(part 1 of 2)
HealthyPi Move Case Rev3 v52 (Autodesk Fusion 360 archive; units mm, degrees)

design "HealthyPi Move Case Rev3" references "Display assembly", "pc_healthypi_move_sensor_dual", "pc_healthypi_move_bottom_pcb_v2", "pc_healthypi_move_nRF5340_v3"
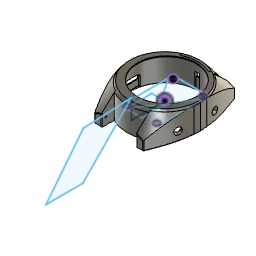
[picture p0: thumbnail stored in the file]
sketch "Main Body" plane through (0, 0, 0) normal (0, 0, 1) x axis (1, 0, 0)
  line L1 (30, -0.1178) -> (0, -0.1178)
  line L2 (0, 22) -> (0, 0)
  line L3 (0, 27.5644) -> (0, 22)
  line L4 (0, 22) -> (0, 27.5644)
  line L5 (10.6623, 27.5644) -> (0, 27.5644)
  line L6 (0, 27.5644) -> (10.6623, 27.5644)
  line L7 (10.6623, 35) -> (10.6623, 27.5644)
  line L8 (10.6623, 27.5644) -> (10.6623, 35)
  line L9 (10.6623, 19.0081) -> (10.6623, 27.5644)
  line L10 (10.6623, 27.5644) -> (10.6623, 19.0081)
  line L11 (15.1791, 27.5644) -> (10.6623, 27.5644)
  curve K1 (21.9997, -0.1178) -> (15.1791, 27.5644)
  curve K2 (22.274, -3.701) -> (21.7253, 3.4655)
  curve K3 (17.031, 22.6753) -> (13.3272, 32.4535)
  curve K4 (-21.9997, -0.1178) -> (-15.1791, 27.5644)
  curve K5 (-17.031, 22.6753) -> (-13.3272, 32.4535)
  curve K6 (-22.274, -3.701) -> (-21.7253, 3.4655)
  line L12 (-10.6623, 19.0081) -> (-10.6623, 27.5644)
  line L13 (-15.1791, 27.5644) -> (-10.6623, 27.5644)
  line L14 (-15.1791, -27.7999) -> (-10.6623, -27.7999)
  line L15 (-10.6623, -19.2436) -> (-10.6623, -27.7999)
  line L16 (10.6623, -19.2436) -> (10.6623, -27.7999)
  line L17 (10.6623, -27.7999) -> (10.6623, -19.2436)
  line L18 (15.1791, -27.7999) -> (10.6623, -27.7999)
  point P1 (0, 0)
  point P4 (0, 0)
  point P11 (21.9997, -0.1178)
  point P10 (15.1791, 27.5644)
  point P7 (10.6623, 27.5644)
  point P22 (-10.6623, 27.5644)
  point P9 (10.6623, 19.0081)
  point P23 (-10.6623, 19.0081)
  point P16 (-15.1791, 27.5644)
  point P17 (-21.9997, -0.1178)
  point P12 (21.7253, 3.4655)
  point P20 (-21.7253, 3.4655)
  point P13 (22.274, -3.701)
  point P21 (-22.274, -3.701)
  point P14 (13.3272, 32.4535)
  point P18 (-13.3272, 32.4535)
  point P15 (17.031, 22.6753)
  point P19 (-17.031, 22.6753)
  point P27 (10.6623, -27.7999)
  point P28 (10.6623, -19.2436)
  point P29 (15.1791, -27.7999)
  point P24 (-15.1791, -27.7999)
  point P25 (-10.6623, -27.7999)
  point P26 (-10.6623, -19.2436)
  horizontal L1
  coincident P1 P4
  perpendicular L1 L2
  parallel L2 L3
  perpendicular L4 L5
  perpendicular L6 L7
  perpendicular L6 L10
  perpendicular L8 L11
  coincident L1 P11
  midpoint P11 K2
  midpoint P10 K3
  symmetric L3 P7 P22
  symmetric L3 P9 P23
  symmetric L3 P10 P16
  symmetric L3 P11 P17
  symmetric L3 P12 P20
  symmetric L3 P13 P21
  symmetric L3 P14 P18
  symmetric L3 P15 P19
  symmetric L1 P7 P27
  symmetric L1 P9 P28
  symmetric L1 P10 P29
  symmetric L1 P16 P24
  symmetric L1 P22 P25
  symmetric L1 P23 P26
component_insert "Component Insert5"
position "Position2"
position "Position3"
position "Position4"
sketch "Bezel" plane through (0, 0, 5.0236) normal (0, 0, 1) x axis (-1, 0, 0)
  circle C1 centre (0.2, -0.9104) radius 18
  circle C2 centre (0, 0) radius 21.5
  circle C3 centre (0.2, -0.803) radius 19.25
  point P1 (0, 0)
  point P3 (0, 0)
  coincident P1 P3
  dimension "d25" diameter C1 = 36
  dimension "d26" diameter C2 = 43
  dimension "d47" diameter C3 = 38.5
extrude "Extrude12" new body sketch "Main Body" profile of L9 L10 L11 K1 K4 L12 L13 L14 L15 L16 L17 L18 along normal blind 10
combine "Combine4"
extrude "Extrude16" new body sketch "Bezel" blind 1 from offset 5 bodies "Bezel"
extrude "Extrude17" cut sketch "Bezel" profile of C1 C3 blind 0.5 from offset 5
position "Position8"
sketch "Sketch7" plane through (0, 0, 5.0236) normal (0, 0, 1) x axis (-1, 0, 0)
  line L1 (-6.8038, 19.9314) -> (-8.7325, 15.7942)
  line L2 (7.3694, 19.9373) -> (-6.8038, 19.9314)
  line L3 (9.3015, 15.8017) -> (7.3694, 19.9373)
  line L4 (-13.4784, -7.3014) -> (-13.4783, -7.4838)
  line L5 (-8.7059, 8.7198) -> (-8.5086, 9.6089)
  line L6 (-8.4449, 8.7199) -> (-8.7059, 8.7198)
  line L7 (-8.351, 9.2142) -> (-8.4449, 8.7199)
  line L8 (-8.2135, 8.72) -> (-8.351, 9.2142)
  line L9 (-7.9548, 8.7201) -> (-8.2135, 8.72)
  line L10 (-7.8171, 9.215) -> (-7.9548, 8.7201)
  line L11 (-7.7222, 8.7202) -> (-7.8171, 9.215)
  line L12 (-7.4624, 8.7204) -> (-7.7222, 8.7202)
  line L13 (-8.2399, 9.609) -> (-8.084, 9.0492)
  line L14 (-8.5086, 9.6089) -> (-8.2399, 9.609)
  line L15 (-6.3267, 8.9653) -> (-6.5836, 8.9652)
  line L16 (-5.8231, 8.9655) -> (-6.0722, 8.9654)
  line L17 (-2.3777, 9.6115) -> (-2.1297, 9.6116)
  line L18 (-7.6716, 12.2436) -> (-7.5008, 12.2437)
  line L19 (-7.6716, 12.072) -> (-7.6716, 12.2436)
  line L20 (-7.5008, 12.0721) -> (-7.6716, 12.072)
  line L21 (-7.5008, 12.2437) -> (-7.5008, 12.0721)
  line L22 (-6.2326, 12.0988) -> (-6.8381, 12.0985)
  line L23 (-6.2326, 12.2442) -> (-6.2326, 12.0988)
  line L24 (-7.0482, 12.2439) -> (-6.2326, 12.2442)
  curve K1 (-6.8648, 11.3801) -> (-7.0482, 12.2439)
  curve K2 (-7.05, 12.163) -> (-7.0482, 12.2439)
  curve K3 (-7.0132, 12.0893) -> (-7.05, 12.163)
  curve K4 (-6.9713, 12.0285) -> (-7.0132, 12.0893)
  curve K5 (-6.9295, 11.9677) -> (-6.9713, 12.0285)
  curve K6 (-6.8825, 11.9197) -> (-6.9295, 11.9677)
  curve K7 (-6.817, 11.8627) -> (-6.8825, 11.9197)
  curve K8 (-6.7515, 11.8057) -> (-6.817, 11.8627)
  curve K9 (-6.6674, 11.7397) -> (-6.7515, 11.8057)
  curve K10 (-6.6014, 11.6792) -> (-6.6674, 11.7397)
  curve K11 (-6.5683, 11.6489) -> (-6.6014, 11.6792)
  curve K12 (-6.5398, 11.62) -> (-6.5683, 11.6489)
  curve K13 (-6.5182, 11.5983) -> (-6.5398, 11.62)
  curve K14 (-6.4966, 11.5767) -> (-6.5182, 11.5983)
  curve K15 (-6.4819, 11.5622) -> (-6.4966, 11.5767)
  curve K16 (-6.4605, 11.5312) -> (-6.4819, 11.5622)
  curve K17 (-6.4391, 11.5001) -> (-6.4605, 11.5312)
  curve K18 (-6.4111, 11.4524) -> (-6.4391, 11.5001)
  curve K19 (-6.3974, 11.4106) -> (-6.4111, 11.4524)
  curve K20 (-6.3838, 11.3688) -> (-6.3974, 11.4106)
  curve K21 (-6.3846, 11.3329) -> (-6.3838, 11.3688)
  curve K22 (-6.3936, 11.299) -> (-6.3846, 11.3329)
  curve K23 (-6.4118, 11.231) -> (-6.3936, 11.299)
  curve K24 (-6.4632, 11.1706) -> (-6.4118, 11.231)
  curve K25 (-6.5363, 11.1463) -> (-6.4632, 11.1706)
  curve K26 (-6.6094, 11.122) -> (-6.5363, 11.1463)
  curve K27 (-6.7042, 11.1337) -> (-6.6094, 11.122)
  curve K28 (-6.7678, 11.175) -> (-6.7042, 11.1337)
  curve K29 (-6.8314, 11.2162) -> (-6.7678, 11.175)
  curve K30 (-6.8638, 11.2871) -> (-6.8314, 11.2162)
  curve K31 (-6.8648, 11.3801) -> (-6.8638, 11.2871)
  line L25 (-7.0193, 11.3646) -> (-6.8648, 11.3801)
  curve K32 (-6.8381, 12.0985) -> (-7.0193, 11.3646)
  curve K33 (-7, 11.1568) -> (-7.0193, 11.3646)
  curve K34 (-6.8702, 11.0355) -> (-7, 11.1568)
  curve K35 (-6.6851, 11.0135) -> (-6.8702, 11.0355)
  curve K36 (-6.5925, 11.0026) -> (-6.6851, 11.0135)
  curve K37 (-6.4862, 11.0164) -> (-6.5925, 11.0026)
  curve K38 (-6.4075, 11.0575) -> (-6.4862, 11.0164)
  curve K39 (-6.3288, 11.0985) -> (-6.4075, 11.0575)
  curve K40 (-6.2777, 11.1668) -> (-6.3288, 11.0985)
  curve K41 (-5.7561, 11.2301) -> (-6.2505, 11.2427)
  curve K42 (-5.7561, 11.2301) -> (-6.2233, 11.3186)
  curve K43 (-6.2199, 11.4021) -> (-6.2233, 11.3186)
  curve K44 (-6.2636, 11.4952) -> (-6.2199, 11.4021)
  curve K45 (-6.2855, 11.5417) -> (-6.2636, 11.4952)
  curve K46 (-6.3191, 11.5906) -> (-6.2855, 11.5417)
  curve K47 (-6.3478, 11.6263) -> (-6.3191, 11.5906)
  curve K48 (-6.3764, 11.662) -> (-6.3478, 11.6263)
  curve K49 (-6.4, 11.6846) -> (-6.3764, 11.662)
  curve K50 (-6.4285, 11.7113) -> (-6.4, 11.6846)
  curve K51 (-6.4569, 11.7381) -> (-6.4285, 11.7113)
  curve K52 (-6.4903, 11.769) -> (-6.4569, 11.7381)
  curve K53 (-6.5334, 11.8067) -> (-6.4903, 11.769)
  curve K54 (-6.5766, 11.8444) -> (-6.5334, 11.8067)
  curve K55 (-6.6295, 11.8888) -> (-6.5766, 11.8444)
  curve K56 (-6.6689, 11.9222) -> (-6.6295, 11.8888)
  curve K57 (-6.7084, 11.9556) -> (-6.6689, 11.9222)
  curve K58 (-6.7344, 11.9779) -> (-6.7084, 11.9556)
  curve K59 (-6.7615, 12.0049) -> (-6.7344, 11.9779)
  curve K60 (-6.7886, 12.0319) -> (-6.7615, 12.0049)
  curve K61 (-6.817, 12.0636) -> (-6.7886, 12.0319)
  curve K62 (-6.8381, 12.0985) -> (-6.817, 12.0636)
  curve K63 (-5.5861, 11.5776) -> (-5.2404, 11.5778)
  curve K64 (-5.148, 11.609) -> (-5.2404, 11.5778)
  curve K65 (-5.082, 11.6618) -> (-5.148, 11.609)
  curve K66 (-5.045, 11.7364) -> (-5.082, 11.6618)
  curve K67 (-5.008, 11.8111) -> (-5.045, 11.7364)
  curve K68 (-5, 11.9074) -> (-5.008, 11.8111)
  curve K69 (-5.0223, 11.9921) -> (-5, 11.9074)
  curve K70 (-5.0447, 12.0767) -> (-5.0223, 11.9921)
  curve K71 (-5.0973, 12.1496) -> (-5.0447, 12.0767)
  curve K72 (-5.1709, 12.1974) -> (-5.0973, 12.1496)
  curve K73 (-5.2444, 12.2453) -> (-5.1709, 12.1974)
  curve K74 (-5.3389, 12.2681) -> (-5.2444, 12.2453)
  curve K75 (-5.4319, 12.2648) -> (-5.3389, 12.2681)
  curve K76 (-5.5249, 12.2615) -> (-5.4319, 12.2648)
  curve K77 (-5.6163, 12.2322) -> (-5.5249, 12.2615)
  curve K78 (-5.6839, 12.18) -> (-5.6163, 12.2322)
  curve K79 (-5.7514, 12.1277) -> (-5.6839, 12.18)
  curve K80 (-5.795, 12.0524) -> (-5.7514, 12.1277)
  curve K81 (-5.8124, 11.9697) -> (-5.795, 12.0524)
  curve K82 (-5.8297, 11.8869) -> (-5.8124, 11.9697)
  curve K83 (-5.8208, 11.7966) -> (-5.8297, 11.8869)
  curve K84 (-5.783, 11.7254) -> (-5.8208, 11.7966)
  curve K85 (-5.7451, 11.6541) -> (-5.783, 11.7254)
  curve K86 (-5.6784, 11.6019) -> (-5.7451, 11.6541)
  curve K87 (-5.5861, 11.5776) -> (-5.6784, 11.6019)
  curve K88 (-5.2404, 11.5778) -> (-5.5861, 11.5776)
  curve K89 (-5.664, 11.5489) -> (-5.5861, 11.5776)
  curve K90 (-5.7174, 11.5063) -> (-5.664, 11.5489)
  curve K91 (-5.7459, 11.4438) -> (-5.7174, 11.5063)
  curve K92 (-5.7744, 11.3813) -> (-5.7459, 11.4438)
  curve K93 (-5.778, 11.2988) -> (-5.7744, 11.3813)
  curve K94 (-5.7561, 11.2301) -> (-5.778, 11.2988)
  curve K95 (-5.7122, 11.0926) -> (-5.7561, 11.2301)
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  point P203 (4.5577, 11.8033)
  point P204 (4.5577, 11.8033)
  coincident P203 P204
extrude "Extrude18" new body sketch "Sketch7" along normal blind 10
move "Move11"
move_face "MoveFace3"
move_face "MoveFace4"
move_face "MoveFace5"
move_face "MoveFace6"
move_face "MoveFace7"
move_face "MoveFace8" TranslateX -65 TranslateY 0 TranslateZ 0
move "Move12" TranslateX -64 TranslateY 0 TranslateZ 0
move "Move13" TranslateX 0 TranslateY 0 TranslateZ -5
move "Move14" TranslateX 0 TranslateY 0 TranslateZ -1
position "Position9"
combine "Combine6"
sketch "Bottom PCB cover" plane through (0, 0, 0) normal (0, 0, 1) x axis (1, 0, 0)
  line L1 (0, 25) -> (0, 0)
  line L2 (25.4334, 0) -> (0, 0)
  circle C1 centre (-0.0004, -0.032) radius 21
  arc A1 centre (13.7643, 16.9724) radius 3.8181 clockwise from (10.1946, 18.3272) to (15.8328, 13.7632)
  circle C2 centre (14.2643, 17.721) radius 1
  arc A2 centre (-13.7643, 16.9724) radius 3.8181 clockwise from (-15.8328, 13.7632) to (-10.1946, 18.3272)
  circle C3 centre (-14.2643, 17.721) radius 1
  arc A3 centre (-13.7643, -16.9724) radius 3.8181 clockwise from (-10.1946, -18.3272) to (-15.8328, -13.7632)
  circle C4 centre (-14.2643, -17.721) radius 1
  arc A4 centre (13.7643, -16.9724) radius 3.8181 clockwise from (15.8328, -13.7632) to (10.1946, -18.3272)
  circle C5 centre (14.2643, -17.721) radius 1
  point P1 (0, 0)
  point P3 (0, 0)
  point P5 (0, 0)
  point P8 (15.8328, 13.7632)
  point P7 (10.1946, 18.3272)
  point P13 (-10.1946, 18.3272)
  point P12 (-15.8328, 13.7632)
  point P22 (10.1946, -18.3272)
  point P21 (15.8328, -13.7632)
  point P18 (-15.8328, -13.7632)
  point P17 (-10.1946, -18.3272)
  coincident P1 P3
  vertical L1
  coincident P1 P5
  perpendicular L1 L2
  coincident C1 P8
  coincident C1 P7
  symmetric L1 P7 P13
  symmetric L1 P8 P12
  symmetric L1 A1 A2
  symmetric L1 C2 C3
  symmetric L2 P7 P22
  symmetric L2 P8 P21
  symmetric L2 A1 A4
  symmetric L2 C2 C5
  symmetric L2 P12 P18
  symmetric L2 P13 P17
  symmetric L2 A2 A3
  symmetric L2 C3 C4
  dimension "d79" diameter C1 = 42
  dimension "d81" diameter C2 = 2
extrude "Extrude19" new body sketch "Bottom PCB cover" profile of C1 A1 C2 along normal blind 1
extrude "Extrude21" new body sketch "Bottom PCB cover" profile of C1 A1 C2 A2 C3 A3 C4 A4 C5 blind 1 from offset -5 bodies "Bottom cover"
move "Move15"
copy_paste_bodies "CopyPasteBodies2"
move "Move16" TranslateX 0 TranslateY 32 TranslateZ 0
move "Move17"
move "Move18"
combine "Combine7" bodies "Bottom cover"
move "Move19"
fillet "Fillet1" radius 1.2
fillet "Fillet2" radius 0.6
delete_face "DeleteFace1"
fillet "Fillet3" radius 0.5
move_face "MoveFace9"
move "Move20"
fillet "Fillet4" radius 0.5
fillet "Fillet5" radius 0.9
component_insert "Component Insert6"
move "Move21"
position "Position10"
sketch "Cutter" plane through (0, 0, 0) normal (1, 0, 0) x axis (0, 1, 0)
  line L1 (-20.5, 0) -> (0, 0)
  line L2 (-73.0459, -18.6004) -> (-50.3996, -18.602)
  line L3 (-73.0459, -18.6004) -> (-50.0889, 10.5658)
  line L4 (-50.0889, 10.5658) -> (-20.5, 12)
  line L5 (-20.5, 12) -> (-20.5, 0)
  line L6 (-50.3996, -18.602) -> (-20.5, 12)
  point P1 (0, 0)
  point P2 (0, 0)
  point P7 (-50.3996, -18.602)
  point P3 (-20.5, 0)
  coincident P1 P2
  horizontal L1
  perpendicular L1 L5
  coincident L2 P7
  dimension "d104" distance P2 P3 = 20.5
move "Move22"
move "Move23"
move "Move24" TranslateX -1 TranslateY 0 TranslateZ 0
revolve "Revolve1" sketch "Cutter" AlongAngle 360 AgainstAngle 0
fillet "Fillet6" radius 0.4
fillet "Fillet7" radius 0.5
offset_faces "OffsetFaces7" distance -4
offset_faces "OffsetFaces8" distance -4
offset_faces "OffsetFaces9" distance -4
offset_faces "OffsetFaces10" distance -4
extrude "Extrude22" cut blind -2
delete_face "DeleteFace2"
cylinder_primitive "CylinderPrimitive1" Height 22 Diameter 1.142
move_face "MoveFace10" TranslateX -2 TranslateY 0 TranslateZ 5
move_face "MoveFace11" TranslateX 0 TranslateY 19 TranslateZ 0
move_face "MoveFace12" TranslateX 0 TranslateY 50 TranslateZ 0
move_face "MoveFace13" TranslateX 0 TranslateY 0 TranslateZ 11
offset_faces "OffsetFaces11" distance 6
move "Move25" TranslateX 3 TranslateY 0 TranslateZ 0
move "Move26" TranslateX 0 TranslateY 0 TranslateZ -11
move "Move27" TranslateX 3 TranslateY 3 TranslateZ -2
move "Move28" TranslateX -3 TranslateY 0 TranslateZ 0
move_face "MoveFace14" TranslateX 0 TranslateY -3 TranslateZ 0
move_face "MoveFace15" TranslateX 0 TranslateY -1 TranslateZ 0
move_face "MoveFace16" TranslateX 45 TranslateY 0 TranslateZ 0
copy_paste_bodies "CopyPasteBodies3"
move "Move29"
move_face "MoveFace17" TranslateX 2 TranslateY 0 TranslateZ 0
move "Move30" TranslateX 1 TranslateY 0 TranslateZ 0
move "Move31" TranslateX -0.5 TranslateY 0 TranslateZ 0
copy_paste_bodies "CopyPasteBodies4"
move "Move32"
combine "Combine8"
combine "Combine9"
fillet "Fillet8" radius 0.4
move "Move33"
move "Move34"
move_face "MoveFace18"
move "Move35"
move "Move36"
position "Position11"
sketch "Sketch18" plane through (0, 0, 11.0236) normal (0, 0, 1) x axis (-1, 0, 0)
  circle C1 centre (0.2, -0.9104) radius 18
  arc A1 centre (0, 0) radius 20 clockwise from (8.1514, 18.2635) to (-7.4412, 18.5642)
  circle C2 centre (0, 0) radius 20.6
offset_faces "OffsetFaces12" distance -0.2
offset_faces "OffsetFaces13" distance -0.2
offset_faces "OffsetFaces14" distance -0.2
offset_faces "OffsetFaces15" distance -0.2
move "Move37"
delete_face "DeleteFace3"
delete_face "DeleteFace4"
delete_face "DeleteFace5"
delete_face "DeleteFace6"
component_insert "Component Insert10"
component_insert "Component Insert11"
offset_faces "OffsetFaces16" distance 4.7
delete_face "DeleteFace7"
offset_faces "OffsetFaces17" sketch "Switch Up" distance -0.25
move "Move38"
move "Move39"
move_face "MoveFace19"
move "Move40"
copy_paste_bodies "CopyPasteBodies5"
move "Move41"
move "Move42"
move "Move43"
position "Position12"
combine "Combine10"
sketch "USB Cutout" plane through (-19.6479, 0, 0) normal (-1, 0, 0) x axis (0, -1, 0)
  line L1 (3.2369, -0.6999) -> (0.8269, -0.6999)
  line L2 (4.5369, 1.1601) -> (4.5369, 0.6001)
  line L3 (-3.1031, 2.4601) -> (3.2369, 2.4601)
  line L4 (-4.4031, 0.6001) -> (-4.4031, 1.1601)
  line L5 (1.8168, -1.7283) -> (-0.1732, -1.7418)
  line L6 (3.2821, -1.6995) -> (1.8168, -1.7283)
  line L7 (5.5369, 1.1601) -> (5.5369, 0.6001)
  line L8 (-3.1031, 3.4601) -> (3.2369, 3.4601)
  line L9 (-5.4031, 0.6001) -> (-5.4031, 1.1601)
  line L10 (-0.1732, -1.7418) -> (-3.1358, -1.6997)
  line L11 (0.8269, -0.6999) -> (-3.1031, -0.6999)
  arc A1 centre (3.2369, 0.6001) radius 1.3 clockwise from (4.5369, 0.6001) to (3.2369, -0.6999)
  arc A2 centre (3.2369, 1.1601) radius 1.3 clockwise from (3.2369, 2.4601) to (4.5369, 1.1601)
  arc A3 centre (-3.1031, 1.1601) radius 1.3 clockwise from (-4.4031, 1.1601) to (-3.1031, 2.4601)
  arc A4 centre (-3.1031, 0.6001) radius 1.3 clockwise from (-3.1031, -0.6999) to (-4.4031, 0.6001)
  arc A5 centre (3.2369, 0.6001) radius 2.3 clockwise from (5.5369, 0.6001) to (3.2821, -1.6995)
  arc A6 centre (3.2369, 1.1601) radius 2.3 clockwise from (3.2369, 3.4601) to (5.5369, 1.1601)
  arc A7 centre (-3.1031, 1.1601) radius 2.3 clockwise from (-5.4031, 1.1601) to (-3.1031, 3.4601)
  arc A8 centre (-3.1031, 0.6001) radius 2.3 clockwise from (-3.1358, -1.6997) to (-5.4031, 0.6001)
  concentric A1 A5
  concentric A2 A6
  concentric A3 A7
  concentric A4 A8
  tangent A8 L10
  tangent L9 A8
  tangent A7 L9
  tangent L8 A7
  tangent L7 A6
  tangent A5 L7
  tangent A6 L8
  tangent L6 A5
  tangent A4 L11
extrude "Extrude23" new body sketch "USB Cutout" profile of L10 A8 L9 A7 L8 A6 L7 A5 L6 along normal blind 6 and along normal blind 5 bodies "USB Offset"
combine "Combine11"
offset_faces "OffsetFaces18" sketch "Switch Up" distance -10
sketch "Side Electrode" plane through (0, 0, 0) normal (0, 1, 0) x axis (1, 0, 0)
  line L1 (9.25, -10) -> (9.25, 0)
  line L2 (-9.25, -10) -> (9.25, -10)
  line L3 (-9.25, -10) -> (-9.25, 0)
  line L4 (-9.25, 0) -> (-9.25, -10)
  line L5 (9.25, -10) -> (9.25, 0)
  line L6 (-9.25, 0) -> (9.25, 0)
  line L7 (9.25, -11) -> (9.25, -10)
  line L8 (-9.25, -11) -> (9.25, -11)
  line L9 (10.6358, -11) -> (9.25, -11)
  line L10 (10.6358, 1.4792) -> (10.6358, -11)
  line L11 (-10.6951, 1.4792) -> (10.6358, 1.4792)
  line L12 (-10.6951, -11) -> (-10.6951, 1.4792)
  line L13 (-9.25, -11) -> (-10.6951, -11)
  line L14 (-1.6047, -5.118) -> (1.3953, -5.118)
  line L15 (-1.6047, -2.118) -> (-1.6047, -5.118)
  line L16 (1.3953, -2.118) -> (-1.6047, -2.118)
  line L17 (1.3953, -5.118) -> (1.3953, -2.118)
  point P2 (9.25, 0)
  point P3 (9.25, -10)
  point P4 (-9.25, -10)
  point P6 (9.25, -11)
  point P7 (-9.25, -11)
  point P12 (1.3953, -5.118)
  point P13 (-1.6047, -5.118)
  point P14 (-1.6047, -2.118)
  perpendicular L1 L2
  perpendicular L4 L6
  perpendicular L2 L7
  perpendicular L7 L8
  perpendicular L7 L9
  perpendicular L8 L10
  perpendicular L10 L11
  perpendicular L11 L12
  perpendicular L12 L13
  parallel L2 L14
  perpendicular L14 L15
  perpendicular L15 L16
  perpendicular L14 L17
  dimension "d191" distance P2 P3 = 10
  dimension "d192" distance P3 P4 = 18.5
  dimension "d357" distance P3 P6 = 1
  dimension "d358" distance P6 P7 = 18.5
  dimension "d397" distance P12 P13 = 3
  dimension "d398" distance P13 P14 = 3
extrude "Extrude26" new body sketch "Side Electrode" profile of L1 L2 L3 along normal blind 1 bodies "Side Electrode"
move "Move44"
offset_faces "OffsetFaces19" distance 1
move_face "MoveFace20"
extrude "Extrude27" new body sketch "Side Electrode" profile of L1 L2 L3 blind 3 from offset 20 bodies "Side Electrode Holder"
move_face "MoveFace21"
move "Move45"
move "Move46"
extrude "Extrude28" cut of existing geometry blind 1
sketch "Bottom Cutout" plane through (0, 0, 0) normal (0, 0, 1) x axis (1, 0, 0)
  line L1 (-15.7, 13.9) -> (-15.9707, 14.0974)
  line L2 (-15.9707, 14.0974) -> (-16.2232, 14.3176)
  line L3 (-10.9272, 19.8796) -> (-10.6949, 19.6383)
  line L4 (-10.6949, 19.6383) -> (-10.4845, 19.3776)
  line L5 (-10, 18.5) -> (-8.2535, 19.3144)
  line L6 (10.4, 18.5) -> (10.5357, 18.8063)
  line L7 (10.8845, 19.3776) -> (11.0949, 19.6383)
  line L8 (11.0949, 19.6383) -> (11.3272, 19.8796)
  line L9 (11.8504, 20.2972) -> (12.1372, 20.4702)
  line L10 (16.1, 13.9) -> (17.236, 12.4195)
  line L11 (16.1, -13.6) -> (16.3707, -13.7974)
  line L12 (17.2527, -14.7977) -> (17.4146, -15.0909)
  line L13 (10.5357, -18.5063) -> (10.4, -18.2)
  line L14 (10.4, -18.2) -> (10, -18.4)
  line L15 (-10, -18.2) -> (-10.1357, -18.5063)
  line L16 (-11.1797, -19.7998) -> (-11.4504, -19.9972)
  line L17 (-15.7, -13.6) -> (-16.836, -12.1195)
  line L18 (-10.3946, 19.9031) -> (-10.1679, 19.6222)
  line L19 (-10.6449, 20.1631) -> (-10.3946, 19.9031)
  line L20 (-16.2743, 13.8315) -> (-16.4925, 14.0218)
  line L21 (-16.2649, -13.5209) -> (-17.1587, -12.3561)
  line L22 (-10.9371, -20.118) -> (-11.2216, -20.3254)
  line L23 (10.2075, -18.7435) -> (10.18, -18.7572)
  line L24 (17.5988, -14.5969) -> (17.7689, -14.9051)
  line L25 (16.6649, 13.8209) -> (17.5586, 12.6561)
  line L26 (11.6365, 20.6353) -> (11.9379, 20.8171)
  line L27 (10.7946, 19.9031) -> (11.0449, 20.1631)
  line L28 (10.5679, 19.6222) -> (10.7946, 19.9031)
  line L29 (-9.8024, 19.0335) -> (-8.4146, 19.6806)
  circle C1 centre (14.4, -17.6) radius 1.25
  circle C2 centre (-14, 17.9) radius 1.25
  circle C3 centre (-14.1, -17.6) radius 1.25
  circle C4 centre (14.45, 17.95) radius 1.25
  arc A1 centre (0.6866, 0.15) radius 21.3912 clockwise from (-16.836, -12.1195) to (-15.7, 13.9)
  arc A2 centre (-13.5752, 17.0986) radius 3.84 clockwise from (-16.2232, 14.3176) to (-10.9272, 19.8796)
  arc A3 centre (-13.5753, 17.0986) radius 3.8401 clockwise from (-10.4845, 19.3776) to (-10, 18.5)
  arc A4 centre (0.2, -1.094) radius 22.0899 clockwise from (-8.2535, 19.3144) to (10.4, 18.5)
  arc A5 centre (13.9751, 17.0985) radius 3.84 clockwise from (10.5357, 18.8063) to (10.8845, 19.3776)
  arc A6 centre (13.9754, 17.0983) radius 3.8404 clockwise from (11.3272, 19.8796) to (11.8504, 20.2972)
  arc A7 centre (13.9752, 17.0986) radius 3.84 clockwise from (12.1372, 20.4702) to (16.1, 13.9)
  arc A8 centre (-0.2867, 0.15) radius 21.3912 clockwise from (17.236, 12.4195) to (16.1, -13.6)
  arc A9 centre (13.9752, -16.7986) radius 3.84 clockwise from (16.3707, -13.7974) to (17.2527, -14.7977)
  arc A10 centre (13.9751, -16.7986) radius 3.84 clockwise from (17.4146, -15.0909) to (10.5357, -18.5063)
  arc A11 centre (0.1921, 0.9099) radius 21.6579 clockwise from (10, -18.4) to (-10, -18.2)
  arc A12 centre (-13.5752, -16.7986) radius 3.84 clockwise from (-10.1357, -18.5063) to (-11.1797, -19.7998)
  arc A13 centre (-13.5752, -16.7986) radius 3.84 clockwise from (-11.4504, -19.9972) to (-15.7, -13.6)
  arc A14 centre (-13.5753, 17.0986) radius 4.2401 clockwise from (-10.1679, 19.6222) to (-9.8024, 19.0335)
  arc A15 centre (-13.5752, 17.0986) radius 4.24 clockwise from (-16.4925, 14.0218) to (-10.6449, 20.1631)
  arc A16 centre (0.6866, 0.15) radius 21.7912 clockwise from (-17.1587, -12.3561) to (-16.2743, 13.8315)
  arc A17 centre (-13.5752, -16.7986) radius 4.24 clockwise from (-11.2216, -20.3254) to (-16.2649, -13.5209)
  arc A18 centre (-13.5752, -16.7986) radius 4.24 clockwise from (-9.8107, -18.7496) to (-10.9371, -20.118)
  arc A19 centre (0.1921, 0.9099) radius 22.0579 clockwise from (10.18, -18.7572) to (-9.8107, -18.7496)
  arc A20 centre (13.9751, -16.7986) radius 4.24 clockwise from (17.7689, -14.9051) to (10.2075, -18.7435)
  arc A21 centre (13.9752, -16.7986) radius 4.24 clockwise from (16.6757, -13.5298) to (17.5988, -14.5969)
  arc A22 centre (-0.2867, 0.15) radius 21.7912 clockwise from (17.5586, 12.6561) to (16.6757, -13.5298)
  arc A23 centre (13.9752, 17.0986) radius 4.24 clockwise from (11.9379, 20.8171) to (16.6649, 13.8209)
  arc A24 centre (13.9754, 17.0983) radius 4.2404 clockwise from (11.0449, 20.1631) to (11.6365, 20.6353)
  arc A25 centre (13.9751, 17.0985) radius 4.24 clockwise from (10.2088, 19.046) to (10.5679, 19.6222)
  arc A26 centre (0.2, -1.094) radius 22.4899 clockwise from (-8.4146, 19.6806) to (10.2088, 19.046)
  dimension "d206" = 0.4
extrude "Extrude29" new body sketch "Bottom Cutout" blind 1 from offset -4 bodies "Bottom Cutout"
move "Move47"
move "Move48"
combine "Combine15" sketch "Switch Up"
extrude "Extrude30" cut sketch "USB Cutout" profile of L1 A1 L2 A2 L3 A3 L4 A4 L11 along normal blind 1
extrude "Extrude31" new body sketch "USB Cutout" profile of L1 A1 L2 A2 L3 A3 L4 A4 L11 along normal blind 5 and against normal blind 5 bodies "USB Cutout"
combine "Combine16"
sketch "Inside Fixture" plane through (0, 0, 0) normal (0, 0, 1) x axis (1, 0, 0)
  line L1 (-11.1264, -14.2668) -> (-11.1259, 14.2778)
  line L2 (9.3235, 16.1831) -> (-9.1186, 16.1823)
  line L3 (11.2736, -14.2669) -> (11.2733, 14.2003)
  line L4 (7.6879, -15.3284) -> (-10.8726, 13.2711)
  line L5 (10.9592, 13.1714) -> (-7.575, -15.3795)
  line L6 (2.0838, -16.0146) -> (-7.9872, -16.0146)
  line L7 (2.0838, 0) -> (2.0838, -16.0146)
  line L8 (-7.9872, 0) -> (2.0838, 0)
  line L9 (-7.9872, -16.0146) -> (-7.9872, 0)
  circle C1 centre (-9.1764, 14.2331) radius 1.25
  circle C2 centre (9.3236, 14.2331) radius 1.25
  circle C3 centre (9.3236, -14.2669) radius 1.25
  circle C4 centre (-9.1764, -14.2669) radius 1.25
  circle C5 centre (-9.1764, 14.2331) radius 1.95
  circle C6 centre (-9.1764, -14.2669) radius 1.95
  circle C7 centre (9.3236, 14.2331) radius 1.95
  circle C8 centre (9.3236, -14.2669) radius 1.95
  point P10 (-11.1259, 14.2778)
  point P11 (-11.1264, -14.2668)
  point P12 (-9.1186, 16.1823)
  point P13 (9.3235, 16.1831)
  point P14 (11.2733, 14.2003)
  point P15 (11.2736, -14.2669)
  point P16 (-10.8726, 13.2711)
  point P17 (7.6879, -15.3284)
  point P18 (-7.575, -15.3795)
  point P19 (10.9592, 13.1714)
  coincident C5 P10
  coincident C6 P11
  tangent C6 L1
  coincident C5 P12
  coincident C7 P13
  tangent C7 L2
  coincident C7 P14
  coincident C8 P15
  tangent C8 L3
  coincident C5 P16
  coincident C8 P17
  tangent C8 L4
  coincident C6 P18
  coincident C7 P19
  tangent C7 L5
  horizontal L6
  vertical L7
  horizontal L8
  vertical L9
  dimension "d246" = 0.7
  dimension "d247" = 0.7
  dimension "d248" = 0.7
  dimension "d249" = 0.7
extrude "Extrude32" new body sketch "Inside Fixture" + "Switch Up" blind 3 from offset 7 bodies "Internal Display holder"
move "Move49"
move "Move50"
extrude "Extrude33" add sketch "Inside Fixture" + "Switch Up" blind 1 from offset 6
move "Move51"
combine "Combine17"
combine "Combine18"
offset_faces "OffsetFaces22" distance -1
fillet "Fillet10" sketch "Switch Up" radius 10
fillet "Fillet11" radius 18
delete_face "DeleteFace8" sketch "Switch Up"
copy_paste_bodies "CopyPasteBodies6"
move "Move52" sketch "Switch Up"
copy_paste_bodies "CopyPasteBodies7"
move "Move53"
copy_paste_bodies "CopyPasteBodies8"
move "Move54" sketch "Switch Up"
offset_faces "OffsetFaces27" distance 5
offset_faces "OffsetFaces28" distance 6
offset_faces "OffsetFaces29" distance -4
combine "Combine20" sketch "Switch Up"
position "Position13"
move_face "MoveFace22"
offset_faces "OffsetFaces30" distance -5
offset_faces "OffsetFaces31" distance 0.7
position "Position14"
extrude "Extrude35" new body sketch "Inside Fixture" profile of C1 C2 C3 C4 along normal blind 1 bodies "Display bench"
extrude "Extrude36" add sketch "Inside Fixture" + "Switch Up" profile of S1:C1 S1:C2 S1:C3 S1:C4 blind -10.5
extrude "Extrude37" new body sketch "Inside Fixture" + "Switch Up" profile of S1:C1 S1:C2 S1:C3 S1:C4 S1:C5 S1:C6 S1:C7 S1:C8 S1:L1 S1:L4 S1:L5 blind -6.9
extrude "Extrude38" add sketch "Inside Fixture" profile of C1 C2 C3 C4 C5 C6 C7 C8 L1 L2 L3 L4 L5 along normal blind 1
sketch "Switch Up" plane through (17.9408, 8.7503, 0) normal (0.8988, 0.4384, 0) x axis (-0.4384, 0.8988, 0)
  circle C1 centre (-0.1243, 0.1978) radius 2
  circle C2 centre (-0.1243, 0.1978) radius 2.1
  circle C3 centre (-0.1243, 0.1978) radius 2.375
  circle C4 centre (-0.1243, 0.1978) radius 2.625
  concentric C1 C3
  concentric C3 C4
  dimension "d289" diameter C1 = 4
  dimension "d294" = 0.1
  dimension "d329" diameter C3 = 4.75
  dimension "d356" diameter C4 = 5.25
sketch "Switch Down" plane through (16.816, -10.5078, 0) normal (0.848, -0.5299, 0) x axis (0.5299, 0.848, 0)
  circle C1 centre (0.4524, 0.2039) radius 2
  circle C2 centre (0.4524, 0.2039) radius 2.1
  circle C3 centre (0.4524, 0.2039) radius 2.375
  circle C4 centre (0.4524, 0.2039) radius 2.625
  concentric C1 C3
  concentric C1 C4
  dimension "d299" diameter C1 = 4
  dimension "d304" = 0.1
  dimension "d330" diameter C3 = 4.75
  dimension "d355" diameter C4 = 5.25
move "Move57"
move "Move58"
extrude "Extrude47" cut sketch "Switch Up" profile of C1 C2 along normal blind 6 and against normal blind 0.5
extrude "Extrude49" cut sketch "Switch Down" profile of C1 C2 along normal blind 7 and against normal blind 0.5
delete_face "DeleteFace9" sketch "Switch Up"
extrude "Extrude50" new body sketch "Switch Up" along normal blind 0.8 and against normal blind 0.5
extrude "Extrude51" cut of existing geometry blind 5
extrude "Extrude52" new body sketch "Switch Down" along normal blind 0.8 and against normal blind 0.5
extrude "Extrude53" cut of existing geometry blind 9
position "Position5"
position "Position6"
position "Position7"
box_primitive "BoxPrimitive1" DistanceX 5 DistanceY 20 DistanceZ 20 OffsetDistanceX 0 OffsetDistanceY 0
move "Move5"
move "Move6"
move_face "MoveFace1"
move_face "MoveFace2"
move "Move7"
move "Move8"
move "Move9"
extrude "Extrude54" new body sketch "Side Electrode" profile of L1 L2 L3 L4 L5 blind 0.5 from offset 20
move "Move59"
move "Move60"
move "Move61"
fillet "Fillet12" radius 0.9
fillet "Fillet13" radius 0.9
sketch "Sketch33" plane through (0, 0, 0) normal (0, 0, 1) x axis (1, 0, 0)
  circle C1 centre (-0.2537, 0.8174) radius 19.25
move "Move62"
move "Move63"
offset_faces "OffsetFaces35" distance -4
extrude "Extrude56" cut sketch "Switch Down" profile of C1 C2 C3 along normal blind 1.5 and against normal blind 0.5
extrude "Extrude57" new body sketch "Switch Down" profile of C1 C2 C3 blind 0.8 from offset 0.7 bodies "SW Act Down"
extrude "Extrude58" add sketch "Switch Down" profile of C1 blind 5 from offset 1.5
extrude "Extrude59" cut sketch "Switch Up" profile of C1 C2 C3 along normal blind 1.5 and against normal blind 0.5
extrude "Extrude60" new body sketch "Switch Up" profile of C1 C2 C3 blind 0.8 from offset 0.7 bodies "SW Act Up"
extrude "Extrude61" add sketch "Switch Up" profile of C1 blind 5 from offset 1.5
move "Move64" sketch "Switch Up"
move "Move65"
extrude "Extrude62" new body sketch "Side Electrode" profile of L1 L2 L3 L4 L5 L6 blind 1 from offset 21 bodies "Electrode"
extrude "Extrude63" new body sketch "Side Electrode" profile of L1 L2 L3 L4 L5 L6 L8 L9 L10 L11 L12 L13 blind 3 from offset 20
offset_faces "OffsetFaces36" distance 1
move "Move66"
move "Move67"
combine "Combine25"
offset_faces "OffsetFaces37" distance 3
copy_paste_bodies "CopyPasteBodies11"
move "Move68"
move "Move69"
offset_faces "OffsetFaces38" distance 1
offset_faces "OffsetFaces39" distance 7
offset_faces "OffsetFaces40" distance 0.9
move "Move70"
extrude "Extrude64" add of existing geometry blind 11.03
delete_face "DeleteFace10"
delete_face "DeleteFace11"
move "Move71" sketch "Switch Up"
move "Move72"
delete_face "DeleteFace12"
delete_face "DeleteFace13"
move "Move73"
move "Move74"
combine "Combine31"
move "Move75"
combine "Combine32"
copy_paste_bodies "CopyPasteBodies12"
move "Move76"
offset_faces "OffsetFaces41" distance 1.41
move "Move77"
offset_faces "OffsetFaces42" distance 1.4
offset_faces "OffsetFaces43" distance 3
offset_faces "OffsetFaces44" distance 4
combine "Combine33" sketch "Switch Up"
fillet "Fillet15" sketch "Switch Up" radius 2
offset_faces "OffsetFaces45" sketch "Switch Up" distance -0.6
fillet "Fillet16" radius 1.55
fillet "Fillet18" sketch "Switch Up" radius 1
fillet "Fillet23" sketch "Switch Up" radius 2.25
extrude "Extrude65" new body sketch "Side Electrode" profile of L14 L15 L16 L17 blind 5 from offset 19
combine "Combine34"
extrude "Extrude66" new body sketch "Side Electrode" profile of L14 L15 L16 L17 blind 1 from offset 20
offset_faces "OffsetFaces46" distance 10
move "Move78"
combine "Combine35"
delete_face "DeleteFace15"
delete_face "DeleteFace16"
combine "Combine36"
sketch "Sketch34" plane through (0, 0, 0) normal (0, 0, 1) x axis (1, 0, 0)
  line L1 (10.6623, -19.4449) -> (10.6623, -27.1999)
  line L2 (-10.6623, -27.1999) -> (-10.6623, -19.8797)
  line L3 (-10.6623, -19.2436) -> (-10.6623, -19.8797)
  line L4 (10.6623, -19.2436) -> (10.6623, -19.4449)
  line L5 (10.6623, -19.2436) -> (10.5539, -19.3032)
  line L6 (10.6623, -18.0688) -> (10.6623, -19.2436)
  line L7 (-10.6623, -17.2035) -> (-10.6623, -19.1577)
  line L8 (-10.6623, -19.2436) -> (-10.6623, -19.1577)
  arc A1 centre (0, 0) radius 22 clockwise from (10.5539, -19.3032) to (-10.2707, -19.4554)
  arc A2 centre (0, 0) radius 22 clockwise from (-10.2707, -19.4554) to (-10.6623, -19.2436)
  arc A3 centre (0, 0) radius 23 clockwise from (11.0336, -20.1807) to (-10.7376, -20.3397)
  arc A4 centre (0, 0) radius 21.4147 clockwise from (10.6623, -18.5716) to (-10.6623, -18.5716)
  point P11 (-10.6623, -19.8797)
  point P13 (-10.6623, -19.8797)
  point P5 (-10.6623, -19.2436)
  point P14 (-10.6623, -19.2436)
  point P10 (10.6623, -19.4449)
  point P15 (10.6623, -19.4449)
  point P8 (10.6623, -19.2436)
  point P16 (10.6623, -19.2436)
  point P3 (10.5539, -19.3032)
  point P17 (10.5539, -19.3032)
  point P21 (10.6623, -19.2436)
  coincident P11 P13
  coincident P5 P14
  coincident P10 P15
  coincident P8 P16
  coincident P3 P17
  coincident P8 P21
  parallel L4 L6
  parallel L3 L7
  concentric A1 A4
  parallel L3 L8
  dimension "d406" = 1
extrude "Extrude67" new body sketch "Sketch34" profile of A1 A2 L1 L2 L3 L4 L5 A3 along normal blind 11 and against normal blind 5.3
delete_face "DeleteFace17" sketch "Switch Up"
delete_face "DeleteFace20"
delete_face "DeleteFace21" sketch "Switch Up"
delete_face "DeleteFace22"
delete_face "DeleteFace23"
delete_face "DeleteFace24" sketch "Switch Up"
delete_face "DeleteFace25"
delete_face "DeleteFace26"
delete_face "DeleteFace27"
delete_face "DeleteFace28" sketch "Switch Up"
delete_face "DeleteFace29"
move "Move80"
extrude "Extrude71" add of existing geometry blind -1
extrude "Extrude72" cut of existing geometry blind -0.9
extrude "Extrude73" cut of existing geometry blind -0.75
delete_face "DeleteFace52"
delete_face "DeleteFace53" sketch "Switch Up"
delete_face "DeleteFace54"
delete_face "DeleteFace55"
delete_face "DeleteFace56"
delete_face "DeleteFace57"
delete_face "DeleteFace58"
delete_face "DeleteFace59"
delete_face "DeleteFace60"
delete_face "DeleteFace61"
delete_face "DeleteFace62" sketch "Switch Up"
delete_face "DeleteFace63"
delete_face "DeleteFace64"
delete_face "DeleteFace65"
delete_face "DeleteFace66"
delete_face "DeleteFace67" sketch "Switch Up"
delete_face "DeleteFace68"
fillet "Fillet24" sketch "Switch Up" radius 0.11
delete_face "DeleteFace30"
delete_face "DeleteFace31"
delete_face "DeleteFace32"
delete_face "DeleteFace33"
delete_face "DeleteFace34"
move "Move79"
delete_face "DeleteFace35"
delete_face "DeleteFace36"
delete_face "DeleteFace37"
delete_face "DeleteFace38"
delete_face "DeleteFace39"
delete_face "DeleteFace40" sketch "Switch Up"
extrude "Extrude68" add of existing geometry blind 1
extrude "Extrude69" add sketch "Sketch34" profile of A1 A2 L5 L6 L7 A4 L8 along normal blind 11
delete_face "DeleteFace41" sketch "Switch Up"
delete_face "DeleteFace42"
delete_face "DeleteFace43"
delete_face "DeleteFace44"
delete_face "DeleteFace45"
delete_face "DeleteFace46"
delete_face "DeleteFace69"
offset_faces "OffsetFaces52" distance -0.1
delete_face "DeleteFace70"
delete_face "DeleteFace71"
delete_face "DeleteFace72"
delete_face "DeleteFace73"
delete_face "DeleteFace74"
offset_faces "OffsetFaces53" distance -0.05
offset_faces "OffsetFaces54" distance 1
delete_face "DeleteFace75"
delete_face "DeleteFace76"
delete_face "DeleteFace77"
delete_face "DeleteFace78"
offset_faces "OffsetFaces55" distance 1.4
offset_faces "OffsetFaces56" distance -1
offset_faces "OffsetFaces57" distance 0.2
extrude "Extrude74" add sketch "Sketch34" profile of A1 A2 L1 L2 L3 L4 L5 A3 along normal blind 11 and against normal blind 5.4
combine "Combine38" sketch "Switch Up" bodies "Bezel"
offset_faces "OffsetFaces58" distance 0.02
revolve "Revolve6" sketch "Cutter" AlongAngle 360
sketch "Sketch35" plane through (-12.5182, -8.7653, 0) normal (-0.8192, -0.5736, 0) x axis (0.5736, -0.8192, 0)
  line L1 (2.3325, 1.885) -> (2.3325, -0.315)
  line L2 (-2.1675, 1.885) -> (2.3325, 1.885)
  line L3 (-2.1675, -0.315) -> (-2.1675, 1.885)
  line L4 (2.3325, -0.315) -> (-2.1675, -0.315)
  line L5 (3.6019, 2.362) -> (-3.4145, 2.362)
  line L6 (3.6019, -0.7611) -> (3.6019, 2.362)
  line L7 (-3.4145, -0.7611) -> (3.6019, -0.7611)
  line L8 (-3.4145, 2.362) -> (-3.4145, -0.7611)
  horizontal L5
  vertical L6
  horizontal L7
  vertical L8
extrude "Extrude75" new body sketch "Sketch35" along normal blind 13
move "Move81"
offset_faces "OffsetFaces59" distance -0.65
delete_face "DeleteFace79"
move "Move82"
delete_face "DeleteFace80"
delete_face "DeleteFace81"
delete_face "DeleteFace82"
combine "Combine40"
delete_face "DeleteFace83"
delete_face "DeleteFace84"
delete_face "DeleteFace85"
delete_face "DeleteFace86"
delete_face "DeleteFace87"
delete_face "DeleteFace88"
offset_faces "OffsetFaces60" distance 0.5
delete_face "DeleteFace89"
delete_face "DeleteFace90"
delete_face "DeleteFace91"
delete_face "DeleteFace92"
offset_faces "OffsetFaces61" distance 0.5
delete_face "DeleteFace93"
delete_face "DeleteFace94"
delete_face "DeleteFace95"
delete_face "DeleteFace96" sketch "Switch Up"
delete_face "DeleteFace97"
sketch "Sketch36" plane through (0, 27.5644, 0) normal (0, 1, 0) x axis (-1, 0, 0)
  line L1 (-11.1623, -5.4) -> (-14.6444, -5.4)
  line L2 (-10.6623, 2.4996) -> (-10.6623, -4.9)
  curve K1 (-10.6623, 2.4996) -> (-15.1791, 0.5488)
  line L3 (-15.1791, -4.9) -> (-15.1791, 0.5488)
  curve K2 (-14.6444, -5.4) -> (-15.1791, -4.9)
  arc A1 centre (-11.1623, -4.9) radius 0.5 clockwise from (-10.6623, -4.9) to (-11.1623, -5.4)
delete_face "DeleteFace98"
delete_face "DeleteFace99"
delete_face "DeleteFace100"
delete_face "DeleteFace101" sketch "Switch Up"
delete_face "DeleteFace102"
delete_face "DeleteFace103"
delete_face "DeleteFace104"
offset_faces "OffsetFaces62" distance 0.5
move "Move83" sketch "Switch Up"
delete_face "DeleteFace105"
delete_face "DeleteFace106"
combine "Combine41"
extrude "Extrude77" cut sketch "Inside Fixture" profile of C4 C6 L4 L5 L6 L7 L8 L9 along normal blind 6 and against normal blind 1
extrude "Extrude78" cut sketch "Inside Fixture" profile of C4 L9 along normal blind 6 and against normal blind 5
fillet "Fillet25" radius 0.5
fillet "Fillet26" radius 0.5
delete_face "DeleteFace107"
delete_face "DeleteFace108"
delete_face "DeleteFace109"
delete_face "DeleteFace110"
delete_face "DeleteFace111"
offset_faces "OffsetFaces63" distance 1
delete_face "DeleteFace112"
offset_faces "OffsetFaces64" distance -0.006
extrude "Extrude11" new body sketch "Main Body" profile of L9 L10 L11 K1 K4 L12 L13 L14 L15 L16 L17 L18 along normal blind 10
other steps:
base_feature "Base Feature2" bodies "Bottom cover", "Bottom cover (1)"
base_feature "Base Feature3"
base_feature "Base Feature4" bodies "Strap pin top"
base_feature "Base Feature5" bodies "Strap pin", "Strap pin (1)"
base_feature "Base Feature6" bodies "Switch Up Cutout", "Switch Up Cutout (1)"
base_feature "Base Feature7" bodies "Switch Down", "Switch Down (1)"
base_feature "Base Feature8" bodies "USB Cutout", "USB Cutout (1)"
base_feature "Base Feature11"
base_feature "Base Feature12" bodies "Electrode", "Electrode (1)"
named bodies: "Main Body", "Bezel", "Bottom cover", "Bottom cover (1)", "Strap pin top", "Strap pin", "Strap pin (1)", "USB Offset", "Side Electrode", "Side Electrode Holder", "Bottom Cutout", "USB Cutout", "Internal Display holder", "Switch Up Cutout", "Switch Up Cutout (1)", "Switch Down", "Switch Down (1)", "USB Cutout (1)", "Display bench", "SW Act Down", "SW Act Up", "Electrode", "Electrode (1)"

design "Display assembly"
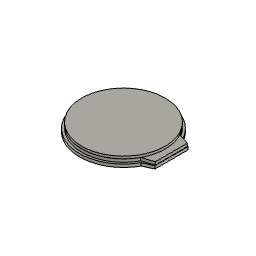
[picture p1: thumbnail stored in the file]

design "pc_healthypi_move_nRF5340_v3"
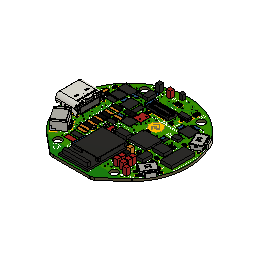
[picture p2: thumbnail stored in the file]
sketch "Outline" plane through (0, 0, 0) normal (0, 0, 1) x axis (1, 0, 0)
  line L1 (12, 0.4) -> (5.1, 6.1)
  line L2 (12.1566, 0.2961) -> (12, 0.4)
  line L3 (13.5, 0) -> (13.4158, -0.0075)
  line L4 (25.4, 0) -> (13.5, 0)
  line L5 (25.5872, 0.0037) -> (25.4, 0)
  line L6 (26.7, 0.4) -> (26.6402, 0.3587)
  line L7 (33.2, 6) -> (26.7, 0.4)
  line L8 (33.3, 6.1) -> (33.2, 6)
  line L9 (4.0077, 31.118) -> (5.1, 32.3969)
  line L10 (5.1, 6.1) -> (4.8727, 6.3481)
  line L11 (2.4, 23.22) -> (1.4, 23.22)
  line L12 (2.4261, 23.2211) -> (2.4, 23.22)
  line L13 (2.4521, 23.2246) -> (2.4261, 23.2211)
  line L14 (2.4777, 23.2302) -> (2.4521, 23.2246)
  line L15 (2.5026, 23.2381) -> (2.4777, 23.2302)
  line L16 (2.5268, 23.2481) -> (2.5026, 23.2381)
  line L17 (2.55, 23.2602) -> (2.5268, 23.2481)
  line L18 (2.5721, 23.2743) -> (2.55, 23.2602)
  line L19 (2.5928, 23.2902) -> (2.5721, 23.2743)
  line L20 (2.6121, 23.3079) -> (2.5928, 23.2902)
  line L21 (2.6298, 23.3272) -> (2.6121, 23.3079)
  line L22 (2.6458, 23.3479) -> (2.6298, 23.3272)
  line L23 (2.6598, 23.37) -> (2.6458, 23.3479)
  line L24 (2.6719, 23.3932) -> (2.6598, 23.37)
  line L25 (2.6819, 23.4174) -> (2.6719, 23.3932)
  line L26 (2.6898, 23.4424) -> (2.6819, 23.4174)
  line L27 (2.6954, 23.4679) -> (2.6898, 23.4424)
  line L28 (2.6989, 23.4939) -> (2.6954, 23.4679)
  line L29 (2.7, 23.52) -> (2.6989, 23.4939)
  line L30 (2.6989, 23.5461) -> (2.7, 23.52)
  line L31 (2.6954, 23.5721) -> (2.6989, 23.5461)
  line L32 (2.6898, 23.5976) -> (2.6954, 23.5721)
  line L33 (2.6819, 23.6226) -> (2.6898, 23.5976)
  line L34 (2.6719, 23.6468) -> (2.6819, 23.6226)
  line L35 (2.6598, 23.67) -> (2.6719, 23.6468)
  line L36 (2.6458, 23.6921) -> (2.6598, 23.67)
  line L37 (2.6298, 23.7128) -> (2.6458, 23.6921)
  line L38 (2.6121, 23.7321) -> (2.6298, 23.7128)
  line L39 (2.5928, 23.7498) -> (2.6121, 23.7321)
  line L40 (2.5721, 23.7657) -> (2.5928, 23.7498)
  line L41 (2.55, 23.7798) -> (2.5721, 23.7657)
  line L42 (2.5268, 23.7919) -> (2.55, 23.7798)
  line L43 (2.5026, 23.8019) -> (2.5268, 23.7919)
  line L44 (2.4777, 23.8098) -> (2.5026, 23.8019)
  line L45 (2.4521, 23.8154) -> (2.4777, 23.8098)
  line L46 (2.4261, 23.8189) -> (2.4521, 23.8154)
  line L47 (2.4, 23.82) -> (2.4261, 23.8189)
  line L48 (1.4, 23.82) -> (2.4, 23.82)
  line L49 (1.3739, 23.8189) -> (1.4, 23.82)
  line L50 (1.3479, 23.8154) -> (1.3739, 23.8189)
  line L51 (1.3223, 23.8098) -> (1.3479, 23.8154)
  line L52 (1.2974, 23.8019) -> (1.3223, 23.8098)
  line L53 (1.2732, 23.7919) -> (1.2974, 23.8019)
  line L54 (1.25, 23.7798) -> (1.2732, 23.7919)
  line L55 (1.2279, 23.7657) -> (1.25, 23.7798)
  line L56 (1.2072, 23.7498) -> (1.2279, 23.7657)
  line L57 (1.1879, 23.7321) -> (1.2072, 23.7498)
  line L58 (1.1702, 23.7128) -> (1.1879, 23.7321)
  line L59 (1.1542, 23.6921) -> (1.1702, 23.7128)
  line L60 (1.1402, 23.67) -> (1.1542, 23.6921)
  line L61 (1.1281, 23.6468) -> (1.1402, 23.67)
  line L62 (1.1181, 23.6226) -> (1.1281, 23.6468)
  line L63 (1.1102, 23.5976) -> (1.1181, 23.6226)
  line L64 (1.1046, 23.5721) -> (1.1102, 23.5976)
  line L65 (1.1011, 23.5461) -> (1.1046, 23.5721)
  line L66 (1.1, 23.52) -> (1.1011, 23.5461)
  line L67 (1.1011, 23.4939) -> (1.1, 23.52)
  line L68 (1.1046, 23.4679) -> (1.1011, 23.4939)
  line L69 (1.1102, 23.4424) -> (1.1046, 23.4679)
  line L70 (1.1181, 23.4174) -> (1.1102, 23.4424)
  line L71 (1.1281, 23.3932) -> (1.1181, 23.4174)
  line L72 (1.1402, 23.37) -> (1.1281, 23.3932)
  line L73 (1.1542, 23.3479) -> (1.1402, 23.37)
  line L74 (1.1702, 23.3272) -> (1.1542, 23.3479)
  line L75 (1.1879, 23.3079) -> (1.1702, 23.3272)
  line L76 (1.2072, 23.2902) -> (1.1879, 23.3079)
  line L77 (1.2279, 23.2743) -> (1.2072, 23.2902)
  line L78 (1.25, 23.2602) -> (1.2279, 23.2743)
  line L79 (1.2732, 23.2481) -> (1.25, 23.2602)
  line L80 (1.2974, 23.2381) -> (1.2732, 23.2481)
  line L81 (1.3223, 23.2302) -> (1.2974, 23.2381)
  line L82 (1.3479, 23.2246) -> (1.3223, 23.2302)
  line L83 (1.3739, 23.2211) -> (1.3479, 23.2246)
  line L84 (1.4, 23.22) -> (1.3739, 23.2211)
  line L85 (2.4, 14.58) -> (1.4, 14.58)
  line L86 (2.4261, 14.5811) -> (2.4, 14.58)
  line L87 (2.4521, 14.5846) -> (2.4261, 14.5811)
  line L88 (2.4777, 14.5902) -> (2.4521, 14.5846)
  line L89 (2.5026, 14.5981) -> (2.4777, 14.5902)
  line L90 (2.5268, 14.6081) -> (2.5026, 14.5981)
  line L91 (2.55, 14.6202) -> (2.5268, 14.6081)
  line L92 (2.5721, 14.6343) -> (2.55, 14.6202)
  line L93 (2.5928, 14.6502) -> (2.5721, 14.6343)
  line L94 (2.6121, 14.6679) -> (2.5928, 14.6502)
  line L95 (2.6298, 14.6872) -> (2.6121, 14.6679)
  line L96 (2.6458, 14.7079) -> (2.6298, 14.6872)
  line L97 (2.6598, 14.73) -> (2.6458, 14.7079)
  line L98 (2.6719, 14.7532) -> (2.6598, 14.73)
  line L99 (2.6819, 14.7774) -> (2.6719, 14.7532)
  line L100 (2.6898, 14.8024) -> (2.6819, 14.7774)
  line L101 (2.6954, 14.8279) -> (2.6898, 14.8024)
  line L102 (2.6989, 14.8539) -> (2.6954, 14.8279)
  line L103 (2.7, 14.88) -> (2.6989, 14.8539)
  line L104 (2.6989, 14.9061) -> (2.7, 14.88)
  line L105 (2.6954, 14.9321) -> (2.6989, 14.9061)
  line L106 (2.6898, 14.9576) -> (2.6954, 14.9321)
  line L107 (2.6819, 14.9826) -> (2.6898, 14.9576)
  line L108 (2.6719, 15.0068) -> (2.6819, 14.9826)
  line L109 (2.6598, 15.03) -> (2.6719, 15.0068)
  line L110 (2.6458, 15.0521) -> (2.6598, 15.03)
  line L111 (2.6298, 15.0728) -> (2.6458, 15.0521)
  line L112 (2.6121, 15.0921) -> (2.6298, 15.0728)
  line L113 (2.5928, 15.1098) -> (2.6121, 15.0921)
  line L114 (2.5721, 15.1257) -> (2.5928, 15.1098)
  line L115 (2.55, 15.1398) -> (2.5721, 15.1257)
  line L116 (2.5268, 15.1519) -> (2.55, 15.1398)
  line L117 (2.5026, 15.1619) -> (2.5268, 15.1519)
  line L118 (2.4777, 15.1698) -> (2.5026, 15.1619)
  line L119 (2.4521, 15.1754) -> (2.4777, 15.1698)
  line L120 (2.4261, 15.1789) -> (2.4521, 15.1754)
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canvas "Canvas1" bodies "Board"
canvas "Canvas2" bodies "Board"
pcbhole "PCBHole1" HoleDepth 0.8 HoleDiameter 2.5 TipAngle 10313.2
pcbhole "PCBHole2" HoleDepth 0.8 HoleDiameter 2.5 TipAngle 10313.2
pcbhole "PCBHole3" HoleDepth 0.8 HoleDiameter 2.5 TipAngle 10313.2
pcbhole "PCBHole4" HoleDepth 0.8 HoleDiameter 2.5 TipAngle 10313.2
pcbhole "PCBHole5" HoleDepth 0.8 HoleDiameter 0.75 TipAngle 10313.2
pcbhole "PCBHole6" HoleDepth 0.8 HoleDiameter 0.75 TipAngle 10313.2
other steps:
base_feature "Base Feature1"
base_feature "Base Feature1"
base_feature "Base Feature1"
box_primitive "BoxPrimitive1" DistanceX 3.505 DistanceY 7.599 DistanceZ 1 OffsetDistanceX 0 OffsetDistanceY 0
base_feature "Base Feature1"
base_feature "Base Feature1"
base_feature "Base Feature1"
box_primitive "BoxPrimitive1" DistanceX 0.75 DistanceY 1.7 DistanceZ 0.1 OffsetDistanceX 0 OffsetDistanceY 0
box_primitive "BoxPrimitive1" DistanceX 2.451 DistanceY 1.351 DistanceZ 0.1 OffsetDistanceX 0 OffsetDistanceY 0
box_primitive "BoxPrimitive1" DistanceX 3.6 DistanceY 1.9 DistanceZ 1 OffsetDistanceX 0 OffsetDistanceY 0
base_feature "Base Feature1"
box_primitive "BoxPrimitive1" DistanceX 14.25 DistanceY 2.04 DistanceZ 0.1 OffsetDistanceX 0 OffsetDistanceY 0
box_primitive "BoxPrimitive1" DistanceX 21.63 DistanceY 6.45 DistanceZ 0.1 OffsetDistanceX 0 OffsetDistanceY 0
box_primitive "BoxPrimitive1" DistanceX 2 DistanceY 3.2 DistanceZ 1 OffsetDistanceX 0 OffsetDistanceY 0
box_primitive "BoxPrimitive1" DistanceX 3.02 DistanceY 1.52 DistanceZ 0.1 OffsetDistanceX 0 OffsetDistanceY 0
box_primitive "BoxPrimitive1" DistanceX 2.865 DistanceY 3.302 DistanceZ 0.1 OffsetDistanceX 0 OffsetDistanceY 0
box_primitive "BoxPrimitive1" DistanceX 1.5 DistanceY 4.7 DistanceZ 1.067 OffsetDistanceX 0 OffsetDistanceY 0
base_feature "Base Feature1"
base_feature "Base Feature1"
box_primitive "BoxPrimitive1" DistanceX 3.9 DistanceY 3.4 DistanceZ 0.1 OffsetDistanceX 0 OffsetDistanceY 0
box_primitive "BoxPrimitive1" DistanceX 1.902 DistanceY 0.902 DistanceZ 0.1 OffsetDistanceX 0 OffsetDistanceY 0
box_primitive "BoxPrimitive1" DistanceX 3.251 DistanceY 1.451 DistanceZ 0.1 OffsetDistanceX 0 OffsetDistanceY 0
box_primitive "BoxPrimitive1" DistanceX 2.93 DistanceY 1.503 DistanceZ 0.1 OffsetDistanceX 0 OffsetDistanceY 0
box_primitive "BoxPrimitive1" DistanceX 3.048 DistanceY 3.8 DistanceZ 0.1 OffsetDistanceX 0 OffsetDistanceY 0
box_primitive "BoxPrimitive1" DistanceX 2.997 DistanceY 1.017 DistanceZ 0.1 OffsetDistanceX 0 OffsetDistanceY 0
box_primitive "BoxPrimitive1" DistanceX 4.735 DistanceY 2.55 DistanceZ 0.1 OffsetDistanceX 0 OffsetDistanceY 0
base_feature "Base Feature1"
box_primitive "BoxPrimitive1" DistanceX 2.8 DistanceY 1.8 DistanceZ 1 OffsetDistanceX 0 OffsetDistanceY 0
box_primitive "BoxPrimitive1" DistanceX 2.9 DistanceY 3.6 DistanceZ 1 OffsetDistanceX 0 OffsetDistanceY 0
box_primitive "BoxPrimitive1" DistanceX 3.297 DistanceY 2.7 DistanceZ 0.1 OffsetDistanceX 0 OffsetDistanceY 0
base_feature "Base Feature1"
base_feature "Base Feature1"
box_primitive "BoxPrimitive1" DistanceX 2 DistanceY 1.5 DistanceZ 0.752 OffsetDistanceX 0 OffsetDistanceY 0
box_primitive "BoxPrimitive1" DistanceX 1.1 DistanceY 1.1 DistanceZ 1.654 OffsetDistanceX 0 OffsetDistanceY 0
box_primitive "BoxPrimitive1" DistanceX 1.3 DistanceY 1.3 DistanceZ 2.184 OffsetDistanceX 0 OffsetDistanceY 0
base_feature "Base Feature1"
extrude "Extrude1" sketch "Outline" blind 0.8 bodies "Board"
pcbextrude "PCBExtrude1"
create_component "CreateComponent1"
create_component "CreateComponent2"
create_component "CreateComponent1"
